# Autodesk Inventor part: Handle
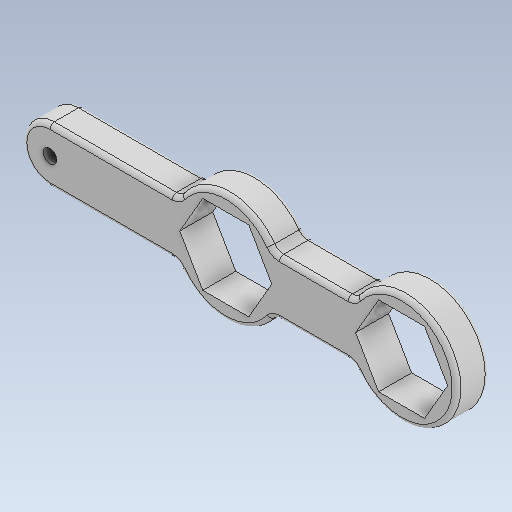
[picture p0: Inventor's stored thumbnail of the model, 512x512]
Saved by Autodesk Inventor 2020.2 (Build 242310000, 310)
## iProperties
Created: 2019-12
Part Number: Handle
Material: Generic
Document SubType Name: Modeling
Designer: Patrick Everitt
Density: 1 g/cm^3
Appearance: Default
Description: 3/4 x 3 CRS 10 lg
Author: Patrick Everitt
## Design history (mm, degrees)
sketch "Sketch1"
  geometry: L1 (26.58, 0)-(13.29, -23.019); L2 (13.29, -23.019)-(-13.29, -23.019); L3 (-13.29, -23.019)-(-26.58, 0); L4 (-26.58, 0)-(-13.29, 23.019); L5 (-13.29, 23.019)-(13.29, 23.019); L6 (13.29, 23.019)-(26.58, 0); L7 (30.946, 15.875)-(70.654, 15.875); L8 (128.18, 0)-(114.89, -23.019); L9 (114.89, -23.019)-(88.31, -23.019); L10 (88.31, -23.019)-(75.02, 0); L11 (75.02, 0)-(88.31, 23.019); L12 (88.31, 23.019)-(114.89, 23.019); L13 (114.89, 23.019)-(128.18, 0); L14 (-101.6, 15.875)-(-30.946, 15.875); L15 (-101.6, -15.875)-(-30.946, -15.875); L16 (30.946, -15.875)-(70.654, -15.875); A1 r 31.75 centre (101.6, 0) between (75.812, -18.521) and (75.812, 18.521); A2 r 15.875 centre (-101.6, 0) between (-101.6, 15.875) and (-101.6, -15.875); A3 r 31.75 centre (0, 0) between (-25.788, -18.521) and (25.788, -18.521); A4 r 31.75 centre (0, 0) between (25.788, 18.521) and (-25.788, 18.521); A5 r 6.35 centre (70.654, 22.225) between (70.654, 15.875) and (75.812, 18.521); A6 r 6.35 centre (70.654, -22.225) between (75.812, -18.521) and (70.654, -15.875); A7 r 6.35 centre (30.946, -22.225) between (30.946, -15.875) and (25.788, -18.521); A8 r 6.35 centre (-30.946, -22.225) between (-25.788, -18.521) and (-30.946, -15.875); A9 r 6.35 centre (-30.946, 22.225) between (-30.946, 15.875) and (-25.788, 18.521); A10 r 6.35 centre (30.946, 22.225) between (25.788, 18.521) and (30.946, 15.875); 13 further points
  constraints: 32 end point, 26 point on circle, 12 tangent, 10 centre point, 6 point on line, 5 coincident, 5 equal radius, 4 horizontal, 26 other
  dimensions: "d0" = 46.0375 distance from line of L2.end L5; "d2" = 15.875 distance from line of L7 L1.start; "d4" = 46.0375 distance from line of L9.end L12; "d5" = 63.5 diameter of A1 (= 2 x d13); "d11" = 31.75 distance between parallel lines of L15 L14 (= 2 x d10); "d12" = 15.875 radius of A2; "d14" = 31.75 radius of A4; "d24" = 6.35 radius of A5 (derived); "d27" = 250.825 dimension on A1 A2
extrude "Extrusion1" new body sketch "Sketch1" distance "d15" = 19.05; taper "d16" = 0 deg
sketch "Sketch2"
  geometry: 2 further points
hole "Hole1" sketch "Sketch2" at (101.6, 0) diameter "d17" = 7.7978; stored, may be unused: countersink angle "d21" = 82 deg, drill point angle "d23" = 118 deg; dims "d18" = 19.05, "d19" = 9.525, "d20" = 6.35, "d22" = 27.0002
fillet "Fillet2" dims "d26" = 2.54
body "Solid1"
other parameters: "d1" = 63.5, "d3" = 31.75 (= 2 x d2), "d10" = 15.875, "d13" = 31.75
